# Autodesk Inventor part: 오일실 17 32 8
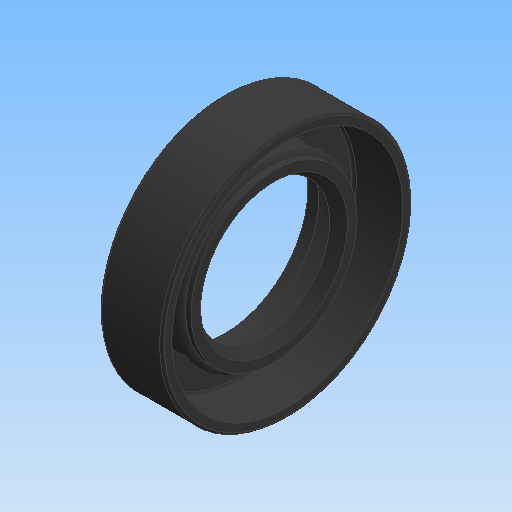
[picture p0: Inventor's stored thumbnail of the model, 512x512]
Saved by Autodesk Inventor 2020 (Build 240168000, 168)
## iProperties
Created: 2024-09
Part Number: 오일실 17 32 8
Material: 고무
Description: 오일-실
Document SubType Name: Modeling
Designer: oem
Density: 0.93 g/cm^3
Appearance: 기본값
Author: jhkim
Sending System: Autodesk Inventor 2025
Preprocessor: ST-DEVELOPER v20
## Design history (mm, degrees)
feature "Solid1"
node "솔리드1"
